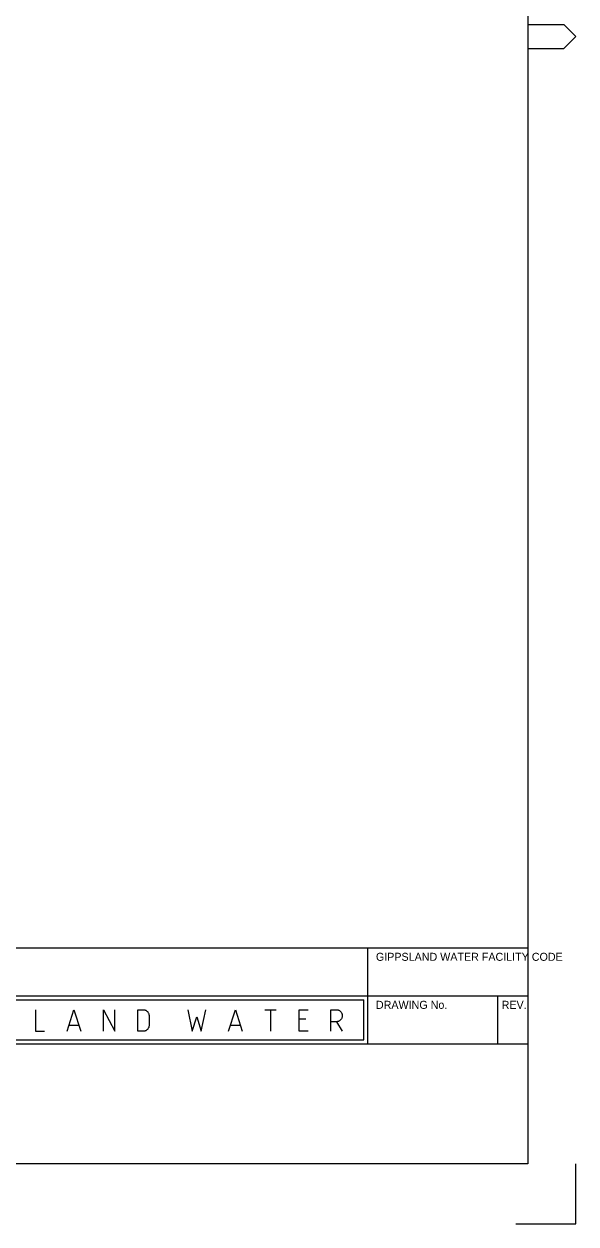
# Model space of a CAD drawing. Extents: x 841 to 1682, y 0 to 594.
# Drawn here: x 1544.1 to 1682, y 0 to 299.9 of the extents above; entities that cross this region are included whole.
import ezdxf

# ---------------------------------------------------------------- set-up
doc = ezdxf.new("R2010")
doc.units = 0
doc.layers.add('A1BORDER', color=7, linetype='Continuous')

msp = doc.modelspace()

# ---------------------------------------------------------------- linework, layer by layer
at = {"layer": 'A1BORDER'}
for p, q in [((1670, 581), (1670, 15)), ((1670, 299.76), (1679, 299.76)), ((1679, 299.76), (1682, 296.76)), ((1679, 293.76), (1682, 296.76)), ((1670, 293.76), (1679, 293.76)), ((1433.5, 69), (1670, 69)), ((1630, 45), (1630, 69)), ((869, 57), (1670, 57)), ((1662.5, 45), (1662.5, 57)), ((1478, 56), (1629, 56)), ((1629, 46), (1629, 56)), ((1504, 46), (1629, 46)), ((1505, 45), (1670, 45)), ((1670, 15), (869, 15)), ((1670, 15), (1670, 15)), ((1682, 0), (1682, 15)), ((1667, 0), (1682, 0))]:
    msp.add_line(p, q, dxfattribs=at)
for points in [[(1546.96, 53.54), (1546.96, 48.16), (1549.23, 48.16)], [(1554.91, 48.16), (1556.61, 53.54), (1558.32, 48.16)], [(1563.99, 48.16), (1563.99, 53.54), (1566.83, 48.16), (1566.83, 53.54)], [(1572.52, 48.16), (1572.52, 53.54), (1573.94, 53.54), (1574.06, 53.54), (1574.18, 53.52), (1574.3, 53.49), (1574.42, 53.45), (1574.53, 53.4), (1574.64, 53.34), (1574.75, 53.27), (1574.84, 53.19), (1574.94, 53.1), (1575.02, 53), (1575.09, 52.9), (1575.16, 52.79), (1575.22, 52.67), (1575.27, 52.56), (1575.31, 52.43), (1575.33, 52.31), (1575.35, 52.18), (1575.36, 52.05), (1575.36, 49.66), (1575.35, 49.52), (1575.33, 49.39), (1575.31, 49.27), (1575.27, 49.14), (1575.22, 49.02), (1575.16, 48.91), (1575.09, 48.8), (1575.02, 48.7), (1574.94, 48.6), (1574.84, 48.51), (1574.75, 48.43), (1574.64, 48.36), (1574.53, 48.3), (1574.42, 48.25), (1574.3, 48.21), (1574.18, 48.18), (1574.06, 48.16), (1573.94, 48.16), (1572.52, 48.16)], [(1585.01, 53.54), (1586.14, 48.16), (1587.28, 51.75), (1588.41, 48.16), (1589.55, 53.54)], [(1595.22, 48.16), (1596.92, 53.54), (1598.63, 48.16)], [(1604.31, 53.54), (1607.15, 53.54)], [(1605.73, 53.54), (1605.73, 48.16)], [(1615.09, 48.16), (1612.82, 48.16), (1612.82, 53.54), (1615.09, 53.54)], [(1614.53, 51.15), (1612.82, 51.15)], [(1620.78, 48.16), (1620.78, 53.54), (1622.2, 53.54), (1622.32, 53.54), (1622.44, 53.52), (1622.56, 53.49), (1622.68, 53.45), (1622.79, 53.4), (1622.9, 53.34), (1623.01, 53.27), (1623.1, 53.19), (1623.2, 53.1), (1623.28, 53), (1623.35, 52.9), (1623.42, 52.79), (1623.48, 52.67), (1623.53, 52.56), (1623.56, 52.43), (1623.59, 52.31), (1623.61, 52.18), (1623.61, 52.05), (1623.61, 51.91), (1623.59, 51.78), (1623.56, 51.66), (1623.53, 51.53), (1623.48, 51.42), (1623.42, 51.3), (1623.35, 51.19), (1623.28, 51.09), (1623.2, 50.99), (1623.1, 50.9), (1623.01, 50.82), (1622.9, 50.75), (1622.79, 50.69), (1622.68, 50.64), (1622.56, 50.6), (1622.44, 50.57), (1622.32, 50.55), (1622.2, 50.55), (1620.78, 50.55)], [(1555.48, 49.66), (1557.75, 49.66)], [(1595.79, 49.66), (1598.06, 49.66)], [(1622.2, 50.55), (1623.61, 48.16)]]:
    msp.add_lwpolyline(points, dxfattribs=at)

# ---------------------------------------------------------------- texts
for s, height, p in [('GIPPSLAND WATER FACILITY CODE', 1.99998, (1632.03, 65.77)), ('DRAWING No.', 1.99998, (1632.03, 53.77)), ('REV.', 2, (1663.43, 53.77))]:
    msp.add_text(s, height=height, dxfattribs=at).set_placement(p)

doc.saveas('drawing.dxf')
